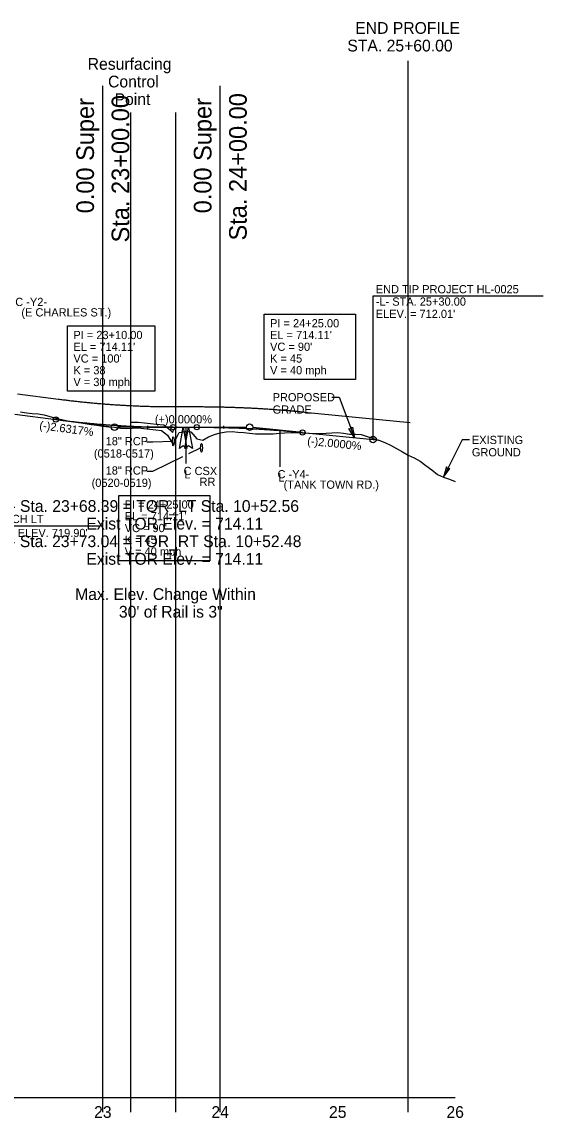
# Model space of a CAD drawing. Extents: x 1518255 to 1527303, y 471773 to 504546.
# Drawn here: x 1520802 to 1521245, y 501127 to 502061 of the extents above; entities that cross this region are included whole.
import ezdxf

# ---------------------------------------------------------------- set-up
doc = ezdxf.new("R2010")
doc.units = 0
for name, color, linetype in [('Exist Profile Cell', 7, 'Continuous'), ('Exist Vertical Profile Ground Line', 7, 'Continuous'), ('Exist Vertical Profile Horizontal Axis Label Major', 7, 'Continuous'), ('Prop Dimension', 7, 'Continuous'), ('Prop Grid Mask', 7, 'Continuous'), ('Prop PFL Cross Pipe CELL', 7, 'Continuous'), ('Prop PFL Cross Pipe Text CELL', 7, 'Continuous'), ('Prop PFL Ditch Label CELL', 7, 'Continuous'), ('Prop Terminator CELL', 7, 'Continuous'), ('Prop Vertical Profile Curve Label', 7, 'Continuous'), ('Prop Vertical Profile Grade', 7, 'Continuous'), ('Prop Vertical Profile Grade Label', 7, 'Continuous'), ('Prop VPI Label', 7, 'Continuous'), ('Scratch_Level_1', 7, 'Continuous'), ('Scratch_Level_2', 7, 'Continuous'), ('Scratch_Level_5', 7, 'Continuous'), ('Scratch_Level_6', 7, 'Continuous'), ('Scratch_Level_7', 7, 'Continuous')]:
    doc.layers.add(name, color=color, linetype=linetype)

msp = doc.modelspace()

# ---------------------------------------------------------------- linework, layer by layer
at = {"layer": 'Exist Profile Cell'}
msp.add_line((1519570.42, 501145.02), (1521170.42, 501145.02), dxfattribs=at)
at = {"layer": 'Exist Vertical Profile Ground Line'}
for points in [[(1520800.42, 501728.53), (1520805.42, 501727.89), (1520810.42, 501727.35), (1520815.42, 501727), (1520820.42, 501726.13), (1520825.42, 501724.74), (1520830.42, 501723.35), (1520835.42, 501721.98), (1520840.42, 501720.89), (1520845.42, 501720.17), (1520850.42, 501719.46), (1520855.42, 501718.75), (1520860.42, 501717.98), (1520865.42, 501717.18), (1520870.42, 501716.4), (1520875.42, 501715.85), (1520880.42, 501715.57), (1520885.42, 501714.85), (1520890.42, 501714.43), (1520895.42, 501714.85), (1520900.42, 501714.92), (1520905.42, 501714.44), (1520910.42, 501713.76), (1520915.42, 501713.23), (1520920.42, 501712.77), (1520925.42, 501708.87), (1520930.42, 501700.97), (1520935.42, 501711.09), (1520940.42, 501712), (1520945.42, 501711.49), (1520950.42, 501705.8), (1520955.42, 501704.65), (1520960.42, 501707.45), (1520965.42, 501709.44), (1520970.42, 501710.73), (1520975.42, 501711.74), (1520980.42, 501711.91), (1520985.42, 501711.43), (1520990.42, 501710.95), (1520995.42, 501710.48), (1521000.42, 501710.05), (1521005.42, 501709.93), (1521010.42, 501709.88), (1521015.42, 501709.96), (1521020.42, 501710.55), (1521025.42, 501710.8), (1521030.42, 501710.99), (1521035.42, 501710.94), (1521040.42, 501710.9), (1521045.42, 501710.6), (1521050.42, 501710.22), (1521055.42, 501710.31), (1521060.42, 501710.52), (1521065.42, 501710.72), (1521070.42, 501710.93)], [(1521070.42, 501710.93), (1521075.42, 501710.53), (1521080.42, 501709.75), (1521085.42, 501709.7), (1521090.42, 501709.48), (1521095.42, 501707.77), (1521100.42, 501706.05), (1521105.42, 501704.43), (1521110.42, 501702.44), (1521115.42, 501700.2), (1521120.42, 501697.46), (1521125.42, 501694.68), (1521130.42, 501691.8), (1521135.42, 501689.58), (1521140.42, 501686.67), (1521145.42, 501683.01), (1521150.42, 501679.15), (1521155.42, 501675.28), (1521160.42, 501672.98), (1521165.42, 501671.33), (1521170.42, 501669.22)]]:
    msp.add_lwpolyline(points, dxfattribs=at)
at = {"layer": 'Prop Dimension'}
for p, q in [((1521065.26, 501741.08), (1521071.65, 501741.08)), ((1521071.65, 501741.08), (1521084.57, 501706.65)), ((1521176.17, 501704.71), (1521160.42, 501672.98)), ((1521182.56, 501704.71), (1521176.17, 501704.71))]:
    msp.add_line(p, q, dxfattribs=at)
at = {"layer": 'Prop Grid Mask'}
for points in [[(1521007.77, 501811.73), (1521085.38, 501811.73), (1521085.38, 501756.19), (1521007.77, 501756.19)], [(1520840.4, 501801.73), (1520914.67, 501801.73), (1520914.67, 501746.19), (1520840.4, 501746.19)], [(1520884.04, 501657.39), (1520961.64, 501657.39), (1520961.64, 501601.85), (1520884.04, 501601.85)]]:
    msp.add_lwpolyline(points, close=True, dxfattribs=at)
at = {"layer": 'Prop PFL Cross Pipe CELL'}
for centre in [(1520930.42, 501703.57), (1520954.42, 501697.92)]:
    msp.add_ellipse(centre, major_axis=(0, -3.75), ratio=0.2, dxfattribs=at)
at = {"layer": 'Prop PFL Cross Pipe Text CELL'}
for p, q in [((1520907.95, 501703.17), (1520912.87, 501703.17)), ((1520912.87, 501703.17), (1520929.67, 501703.57)), ((1520943.68, 501693.09), (1520953.67, 501697.92)), ((1520912.87, 501678.23), (1520938.54, 501690.62)), ((1520907.95, 501678.23), (1520912.87, 501678.23))]:
    msp.add_line(p, q, dxfattribs=at)
at = {"layer": 'Prop PFL Ditch Label CELL'}
msp.add_line((1520698.42, 501631.48), (1520868.57, 501631.48), dxfattribs=at)
at = {"layer": 'Prop Terminator CELL'}
for points in [[(1521082.86, 501715.62), (1521084.57, 501706.65), (1521079.89, 501714.56), (1521081.79, 501714.05)], [(1521163.03, 501681.73), (1521160.42, 501672.98), (1521165.87, 501680.38), (1521163.93, 501680.06)]]:
    msp.add_lwpolyline(points, close=True, dxfattribs=at)
at = {"layer": 'Prop Vertical Profile Curve Label'}
for p, q in [((1521100.42, 501705.07), (1521100.42, 501827.46)), ((1521100.42, 501827.46), (1521245.14, 501827.46)), ((1520941.13, 501715.57), (1520941.13, 501684.65)), ((1521021.11, 501712.79), (1521021.11, 501681.87))]:
    msp.add_line(p, q, dxfattribs=at)
for centre in [(1520830.42, 501722.14), (1520930.42, 501715.57), (1520950.42, 501715.57), (1521040.42, 501711.07)]:
    msp.add_circle(centre, 2.25, dxfattribs=at)
at = {"layer": 'Prop Vertical Profile Grade'}
for p, q in [((1520795.42, 501726.75), (1520830.42, 501722.14)), ((1520930.42, 501715.57), (1520950.42, 501715.57)), ((1521040.42, 501711.07), (1521100.42, 501705.07)), ((1521100.42, 501705.07), (1521104.81, 501704.63))]:
    msp.add_line(p, q, dxfattribs=at)
for points in [[(1520830.42, 501722.14), (1520832.42, 501721.88), (1520834.42, 501721.63), (1520836.42, 501721.38), (1520838.42, 501721.13), (1520840.42, 501720.89), (1520842.42, 501720.66), (1520844.42, 501720.43), (1520846.42, 501720.21), (1520848.42, 501719.99), (1520850.42, 501719.78), (1520852.42, 501719.57), (1520854.42, 501719.37), (1520856.42, 501719.17), (1520858.42, 501718.98), (1520860.42, 501718.79), (1520862.42, 501718.61), (1520864.42, 501718.43), (1520866.42, 501718.26), (1520868.42, 501718.09), (1520870.42, 501717.93), (1520872.42, 501717.78), (1520874.42, 501717.63), (1520876.42, 501717.48), (1520878.42, 501717.34), (1520880.42, 501717.21), (1520882.42, 501717.08), (1520884.42, 501716.96), (1520886.42, 501716.84), (1520888.42, 501716.73), (1520890.42, 501716.62), (1520892.42, 501716.52), (1520894.42, 501716.42), (1520896.42, 501716.33), (1520898.42, 501716.24), (1520900.42, 501716.16), (1520902.42, 501716.08), (1520904.42, 501716.01), (1520906.42, 501715.94), (1520908.42, 501715.88), (1520910.42, 501715.83), (1520912.42, 501715.78), (1520914.42, 501715.73), (1520916.42, 501715.69), (1520918.42, 501715.66), (1520920.42, 501715.63), (1520922.42, 501715.61), (1520924.42, 501715.59), (1520926.42, 501715.58), (1520928.42, 501715.57), (1520930.42, 501715.57)], [(1520950.42, 501715.57), (1520952.22, 501715.56), (1520954.02, 501715.56), (1520955.82, 501715.55), (1520957.62, 501715.54), (1520959.42, 501715.52), (1520961.22, 501715.5), (1520963.02, 501715.48), (1520964.82, 501715.45), (1520966.62, 501715.42), (1520968.42, 501715.39), (1520970.22, 501715.35), (1520972.02, 501715.31), (1520973.82, 501715.26), (1520975.62, 501715.21), (1520977.42, 501715.16), (1520979.22, 501715.1), (1520981.02, 501715.05), (1520982.82, 501714.98), (1520984.62, 501714.92), (1520986.42, 501714.85), (1520988.22, 501714.77), (1520990.02, 501714.69), (1520991.82, 501714.61), (1520993.62, 501714.53), (1520995.42, 501714.44), (1520997.22, 501714.35), (1520999.02, 501714.25), (1521000.82, 501714.15), (1521002.62, 501714.05), (1521004.42, 501713.95), (1521006.22, 501713.84), (1521008.02, 501713.72), (1521009.82, 501713.61), (1521011.62, 501713.48), (1521013.42, 501713.36), (1521015.22, 501713.23), (1521017.02, 501713.1), (1521018.82, 501712.97), (1521020.62, 501712.83), (1521022.42, 501712.69), (1521024.22, 501712.54), (1521026.02, 501712.39), (1521027.82, 501712.24), (1521029.62, 501712.08), (1521031.42, 501711.92), (1521033.22, 501711.76), (1521035.02, 501711.59), (1521036.82, 501711.42), (1521038.62, 501711.24), (1521040.42, 501711.07)]]:
    msp.add_spline(points, degree=3, dxfattribs=at)
at = {"layer": 'Prop VPI Label'}
for p, q in [((1520830.42, 501722.14), (1520877.69, 501715.92)), ((1520930.42, 501715.57), (1520883.17, 501715.57)), ((1520950.42, 501715.57), (1520992.67, 501715.57)), ((1521040.42, 501711.07), (1520998.15, 501715.29))]:
    msp.add_line(p, q, dxfattribs=at)
for centre in [(1520880.42, 501715.57), (1520995.42, 501715.57), (1521100.42, 501705.07), (1521100.42, 501705.07)]:
    msp.add_circle(centre, 2.75, dxfattribs=at)
at = {"layer": 'Scratch_Level_1'}
msp.add_line((1521130.42, 501132.52), (1521130.42, 502027.52), dxfattribs=at)
at = {"layer": 'Scratch_Level_2'}
for p, q in [((1520908.81, 501715.57), (1520908.81, 501716.82)), ((1520908.81, 501715.57), (1520938.81, 501715.57)), ((1520908.81, 501714.32), (1520908.81, 501715.57)), ((1520943.46, 501715.57), (1520973.46, 501715.57)), ((1520973.46, 501715.57), (1520973.46, 501716.82)), ((1520973.46, 501714.32), (1520973.46, 501715.57))]:
    msp.add_line(p, q, dxfattribs=at)
for points in [[(1520935.71, 501697.57), (1520938.81, 501715.57), (1520942.01, 501697.47), (1520938.81, 501699.77)], [(1520940.36, 501697.57), (1520943.46, 501715.57), (1520946.66, 501697.47), (1520943.46, 501699.77)]]:
    msp.add_lwpolyline(points, close=True, dxfattribs=at)
at = {"layer": 'Scratch_Level_5'}
for p, q in [((1520870.42, 501132.52), (1520870.42, 502006.08)), ((1520970.42, 501132.52), (1520970.42, 502006.08))]:
    msp.add_line(p, q, dxfattribs=at)
at = {"layer": 'Scratch_Level_6'}
for p, q in [((1520894.29, 501132.52), (1520894.29, 501983.41)), ((1520932.6, 501132.52), (1520932.6, 501983.41))]:
    msp.add_line(p, q, dxfattribs=at)
msp.add_lwpolyline([(1520894.29, 501719.77), (1520895.17, 501719.84), (1520900.62, 501719.92), (1520905.99, 501719.41), (1520911.01, 501718.72), (1520915.91, 501718.21), (1520922.34, 501717.62), (1520929.18, 501712.27), (1520929.88, 501711.17), (1520932.05, 501715.56), (1520932.6, 501715.66)], dxfattribs=at)
at = {"layer": 'Scratch_Level_7'}
for p, q in [((1520797.7, 501744.1), (1520832.7, 501739.5)), ((1520930.42, 501733.07), (1520950.42, 501733.07)), ((1521042.16, 501728.48), (1521132.16, 501719.48))]:
    msp.add_line(p, q, dxfattribs=at)
for points in [[(1520832.68, 501739.5), (1520834.65, 501739.24), (1520836.61, 501738.99), (1520838.56, 501738.75), (1520840.52, 501738.51), (1520842.47, 501738.27), (1520844.43, 501738.04), (1520846.38, 501737.82), (1520848.34, 501737.6), (1520850.29, 501737.39), (1520852.25, 501737.18), (1520854.2, 501736.98), (1520856.16, 501736.78), (1520858.11, 501736.59), (1520860.07, 501736.4), (1520862.02, 501736.22), (1520863.98, 501736.04), (1520865.93, 501735.87), (1520867.88, 501735.7), (1520869.84, 501735.54), (1520871.79, 501735.38), (1520873.75, 501735.23), (1520875.7, 501735.08), (1520877.66, 501734.94), (1520879.61, 501734.8), (1520881.56, 501734.67), (1520883.52, 501734.55), (1520885.47, 501734.43), (1520887.43, 501734.31), (1520889.38, 501734.2), (1520891.34, 501734.09), (1520893.29, 501733.99), (1520895.24, 501733.9), (1520897.2, 501733.81), (1520899.15, 501733.72), (1520901.11, 501733.64), (1520903.06, 501733.57), (1520905.01, 501733.5), (1520906.97, 501733.44), (1520908.92, 501733.38), (1520910.88, 501733.32), (1520912.83, 501733.27), (1520914.78, 501733.23), (1520916.74, 501733.19), (1520918.69, 501733.16), (1520920.65, 501733.13), (1520922.6, 501733.11), (1520924.55, 501733.09), (1520926.51, 501733.08), (1520928.46, 501733.07), (1520930.44, 501733.07)], [(1520950.43, 501733.07), (1520952.25, 501733.06), (1520954.09, 501733.06), (1520955.92, 501733.05), (1520957.76, 501733.04), (1520959.59, 501733.02), (1520961.43, 501733), (1520963.26, 501732.98), (1520965.1, 501732.95), (1520966.93, 501732.92), (1520968.77, 501732.88), (1520970.6, 501732.84), (1520972.44, 501732.8), (1520974.27, 501732.76), (1520976.11, 501732.71), (1520977.94, 501732.65), (1520979.78, 501732.6), (1520981.61, 501732.54), (1520983.45, 501732.47), (1520985.28, 501732.4), (1520987.12, 501732.33), (1520988.95, 501732.26), (1520990.78, 501732.18), (1520992.62, 501732.09), (1520994.45, 501732.01), (1520996.29, 501731.92), (1520998.12, 501731.82), (1520999.96, 501731.73), (1521001.79, 501731.63), (1521003.63, 501731.52), (1521005.46, 501731.41), (1521007.3, 501731.3), (1521009.13, 501731.19), (1521010.97, 501731.07), (1521012.8, 501730.94), (1521014.64, 501730.82), (1521016.47, 501730.69), (1521018.31, 501730.55), (1521020.14, 501730.42), (1521021.98, 501730.27), (1521023.81, 501730.13), (1521025.65, 501729.98), (1521027.48, 501729.83), (1521029.32, 501729.67), (1521031.15, 501729.51), (1521032.98, 501729.35), (1521034.82, 501729.18), (1521036.65, 501729.01), (1521038.49, 501728.84), (1521040.32, 501728.66), (1521042.14, 501728.48)]]:
    msp.add_spline(points, degree=3, dxfattribs=at)

# ---------------------------------------------------------------- texts
at = {"layer": 'Exist Vertical Profile Horizontal Axis Label Major'}
for s, p in [('23', (1520863.02, 501127.52)), ('24', (1520962.87, 501127.52)), ('25', (1521062.96, 501127.52)), ('26', (1521162.9, 501127.52))]:
    msp.add_text(s, height=10, dxfattribs=at).set_placement(p)
at = {"layer": 'Prop Dimension'}
for s, p in [('PROPOSED', (1521014.96, 501737.59)), ('GRADE', (1521014.96, 501727.09)), ('EXISTING', (1521184.55, 501701.22)), ('GROUND', (1521184.55, 501690.72))]:
    msp.add_text(s, height=7, dxfattribs=at).set_placement(p)
at = {"layer": 'Prop PFL Cross Pipe Text CELL'}
for s, p in [('18" RCP', (1520872.86, 501700.19)), ('(0518-0517)', (1520862.83, 501689.69)), ('18" RCP', (1520872.86, 501675.24)), ('(0520-0519)', (1520860.9, 501664.74))]:
    msp.add_text(s, height=7, dxfattribs=at).set_placement(p)
at = {"layer": 'Prop PFL Ditch Label CELL'}
for s, p in [('END LATERAL V DITCH LT', (1520702.47, 501633.93)), ("-L- STA. 21+28.00 LT, ELEV. 719.90'", (1520702.47, 501622.03))]:
    msp.add_text(s, height=7, dxfattribs=at).set_placement(p)
at = {"layer": 'Prop Vertical Profile Curve Label'}
for s, p in [('END TIP PROJECT HL-0025', (1521102.75, 501829.54)), ('C -Y2-', (1520795.92, 501818.71)), ('-L- STA. 25+30.00', (1521102.75, 501819.04)), ('  (E CHARLES ST.)', (1520795.92, 501809.84)), ("ELEV. = 712.01'", (1521102.75, 501808.54)), ("VC = 90'", (1521012.79, 501780.57)), ("VC = 100'", (1520845.42, 501770.57)), ('K = 45', (1521012.79, 501770.57)), ('K = 38', (1520845.42, 501760.57)), ('V = 40 mph', (1521012.79, 501760.57)), ('V = 30 mph', (1520845.42, 501750.57)), ('C CSX', (1520939.16, 501674.8)), ('L', (1520939.81, 501671.92)), ('C -Y4-', (1521019.13, 501672.03)), ('RR', (1520952.74, 501665.56)), ('L', (1521019.79, 501669.15)), ('  (TANK TOWN RD.)', (1521019.13, 501663.15)), ("VC = 90'", (1520889.06, 501626.23)), ('K = 45', (1520889.06, 501616.23)), ('V = 40 mph', (1520889.06, 501606.23))]:
    msp.add_text(s, height=7, dxfattribs=at).set_placement(p)
at = {"layer": 'Prop Vertical Profile Grade Label'}
msp.add_text('(+)0.0000%', height=7, dxfattribs=at).set_placement((1520914.73, 501718.83))
for s, rotation, p in [('(-)2.6317%', 352.50367, (1520816.12, 501713.94)), ('(-)2.0000%', 354.28941, (1521044.15, 501700.63))]:
    msp.add_text(s, height=7, rotation=rotation, dxfattribs=at).set_placement(p)
at = {"layer": 'Prop VPI Label'}
for s, p in [('PI = 24+25.00', (1521012.79, 501800.57)), ('PI = 23+10.00', (1520845.42, 501790.57)), ("EL = 714.11'", (1521012.79, 501790.57)), ("EL = 714.11'", (1520845.42, 501780.57)), ('PI = 24+25.00', (1520889.06, 501646.23)), ("EL = 714.11'", (1520889.06, 501636.23))]:
    msp.add_text(s, height=7, dxfattribs=at).set_placement(p)
at = {"layer": 'Scratch_Level_1'}
for s, p in [('END PROFILE', (1521085.29, 502050.46)), ('STA. 25+60.00', (1521078.56, 502035.46))]:
    msp.add_text(s, height=10, dxfattribs=at).set_placement(p)
at = {"layer": 'Scratch_Level_2'}
for s, p in [('-L- Sta. 23+68.39 = TOR_LT Sta. 10+52.56', (1520779.86, 501643.46)), ('Exist TOR Elev. = 714.11', (1520856.47, 501628.46)), ('-L- Sta. 23+73.04 = TOR_RT Sta. 10+52.48', (1520779.7, 501613.46)), ('Exist TOR Elev. = 714.11', (1520856.47, 501598.46)), ('Max. Elev. Change Within', (1520846.87, 501568.46)), ('30\' of Rail is 3"', (1520884.11, 501553.46))]:
    msp.add_text(s, height=10, rotation=360, dxfattribs=at).set_placement(p)
at = {"layer": 'Scratch_Level_5'}
for s, p in [('0.00 Super', (1520862.92, 501897.66)), ('Sta. 23+00.00', (1520892.92, 501872.87)), ('0.00 Super', (1520962.92, 501897.66)), ('Sta. 24+00.00', (1520992.92, 501874.52))]:
    msp.add_text(s, height=15, rotation=90, dxfattribs=at).set_placement(p)
at = {"layer": 'Scratch_Level_6'}
for s, p in [('Resurfacing', (1520857.56, 502019.85)), ('Control', (1520874.88, 502004.85)), ('Point', (1520880.43, 501989.85))]:
    msp.add_text(s, height=10, dxfattribs=at).set_placement(p)

doc.saveas('drawing.dxf')
